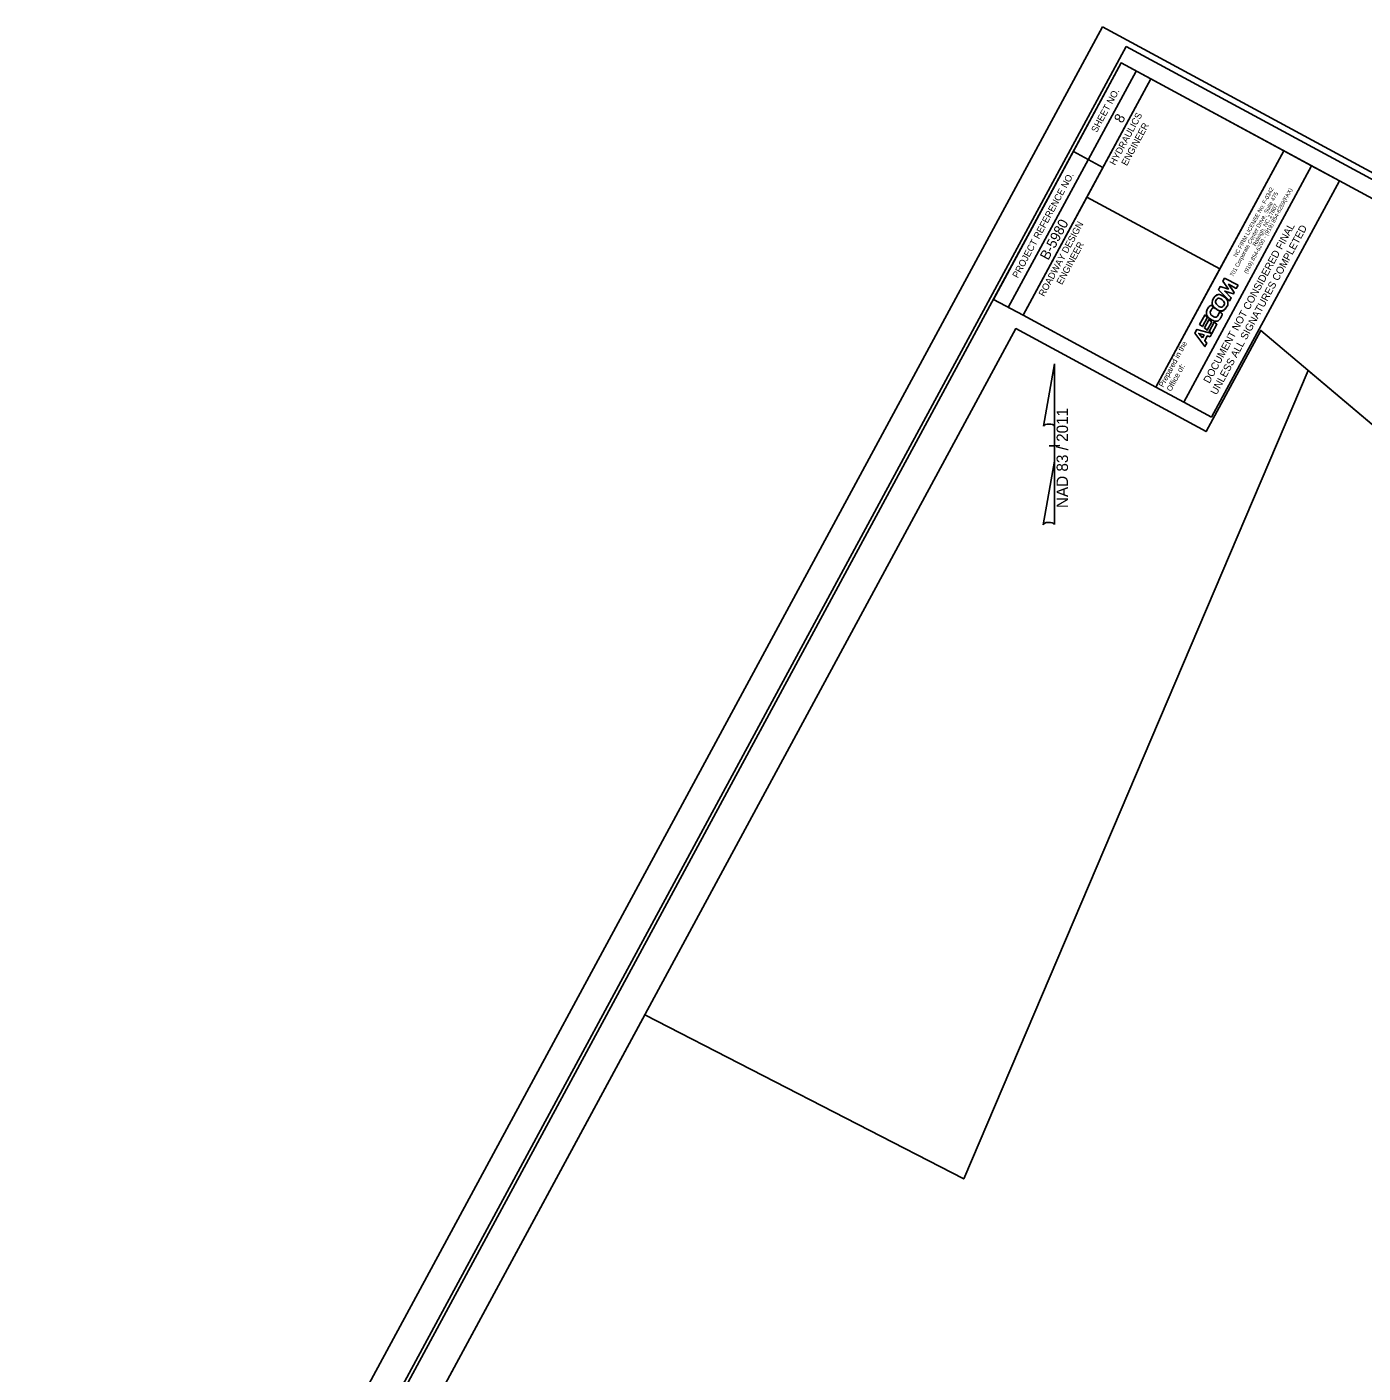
# Model space of a CAD drawing. Extents: x 2345885 to 2347654, y 842598 to 844603.
# Drawn here: x 2345885 to 2346880, y 843601 to 844603 of the extents above; entities that cross this region are included whole.
import ezdxf

# ---------------------------------------------------------------- set-up
doc = ezdxf.new("R2010")
doc.units = 0
for name, color, linetype in [('Default', 7, 'Continuous'), ('Old_Level_49', 7, 'Continuous'), ('Prop North Arrow NAD83 for Plan Sheets CELL', 7, 'Continuous'), ('Sheet Border Standard 30in CELL', 7, 'Continuous'), ('Sheet Clip Boundary CELL', 7, 'Continuous'), ('Sheet Data Field CELL', 7, 'Continuous'), ('Sheet Plot Border Inside CELL', 7, 'Continuous'), ('Sheet Plot Border Outside CELL', 7, 'Continuous'), ('Sheet Profile CELL', 7, 'Continuous'), ('Sheet Sticker Exception Certification CELL', 7, 'Continuous')]:
    doc.layers.add(name, color=color, linetype=linetype)

# ---------------------------------------------------------------- blocks, each defined once
blk = doc.blocks.new('block 2')
at = {"layer": 'Default'}
for p, q in [((0.10234, 0.09375), (0.10197, 0.09133)), ((0.10966, 0.09375), (0.10234, 0.09375)), ((0.10929, 0.09133), (0.10966, 0.09375)), ((0.10114, 0.08576), (0.10078, 0.08333)), ((0.10078, 0.08333), (0.1081, 0.08333)), ((0.10846, 0.08576), (0.10114, 0.08576)), ((0.10137, 0.08733), (0.10174, 0.08975)), ((0.10782, 0.08733), (0.10137, 0.08733)), ((0.10174, 0.08975), (0.10818, 0.08975)), ((0.10197, 0.09133), (0.10929, 0.09133)), ((0.10818, 0.08975), (0.10782, 0.08733)), ((0.1081, 0.08333), (0.10846, 0.08576))]:
    blk.add_line(p, q, dxfattribs=at)
for points in [[(0.10929, 0.09133), (0.10197, 0.09133), (0.10234, 0.09375), (0.10966, 0.09375), (0.10929, 0.09133)], [(0.10846, 0.08576), (0.10114, 0.08576), (0.10078, 0.08333), (0.1081, 0.08333), (0.10846, 0.08576)], [(0.10782, 0.08733), (0.10137, 0.08733), (0.10174, 0.08975), (0.10818, 0.08975), (0.10782, 0.08733)]]:
    blk.add_lwpolyline(points, dxfattribs=at)
blk = doc.blocks.new('block 3')
at = {"layer": 'Default'}
blk.add_open_spline([(0.12275, 0.09393), (0.12554, 0.09373), (0.12726, 0.09146), (0.12695, 0.08843), (0.12663, 0.08531), (0.12411, 0.08298), (0.12127, 0.08318), (0.11848, 0.08338), (0.11676, 0.08565), (0.11707, 0.08868), (0.11739, 0.0918), (0.11991, 0.09413), (0.12275, 0.09393)], degree=3, dxfattribs=at)

msp = doc.modelspace()

# ---------------------------------------------------------------- linework, layer by layer
at = {"layer": 'Old_Level_49'}
for p, q in [((2346773.3, 844409.6), (2346772.1, 844407.3)), ((2346772.1, 844407.3), (2346780.3, 844398.9)), ((2346779.5, 844407.7), (2346773.3, 844409.6)), ((2346776.7, 844415.8), (2346775.5, 844413.6)), ((2346775.5, 844413.6), (2346779.5, 844407.7)), ((2346786.7, 844410.6), (2346776.7, 844415.8)), ((2346783.8, 844405.3), (2346779.6, 844411.4)), ((2346779.6, 844411.4), (2346785.4, 844408.2)), ((2346785.4, 844408.2), (2346786.7, 844410.6)), ((2346781.7, 844401.3), (2346776.8, 844406.2)), ((2346776.8, 844406.2), (2346783.2, 844404.1)), ((2346780.3, 844398.9), (2346781.7, 844401.3)), ((2346783.2, 844404.1), (2346783.8, 844405.3)), ((2346756.1, 844377.7), (2346754.6, 844375)), ((2346767.2, 844374.6), (2346756.1, 844377.7)), ((2346754.6, 844375), (2346762, 844364.9)), ((2346760.2, 844371.4), (2346757.5, 844374.7)), ((2346757.5, 844374.7), (2346757.5, 844374.7)), ((2346757.5, 844374.7), (2346761.4, 844373.6)), ((2346761.4, 844373.6), (2346760.2, 844371.4)), ((2346761.9, 844369.3), (2346763.8, 844372.9)), ((2346763.4, 844367.4), (2346761.9, 844369.3)), ((2346762, 844364.9), (2346763.4, 844367.4)), ((2346763.8, 844372.9), (2346766, 844372.2)), ((2346766, 844372.2), (2346767.2, 844374.6))]:
    msp.add_line(p, q, dxfattribs=at)
for points in [[(2346786.7, 844410.6), (2346776.7, 844415.8), (2346775.5, 844413.6), (2346779.5, 844407.7), (2346773.3, 844409.6), (2346772.1, 844407.3), (2346780.3, 844398.9), (2346781.7, 844401.3), (2346776.8, 844406.2), (2346783.2, 844404.1), (2346783.8, 844405.3), (2346779.6, 844411.4), (2346785.4, 844408.2), (2346786.7, 844410.6)], [(2346766, 844372.2), (2346767.2, 844374.6), (2346756.1, 844377.7), (2346754.6, 844375), (2346762, 844364.9), (2346763.4, 844367.4), (2346761.9, 844369.3), (2346763.8, 844372.9), (2346766, 844372.2)], [(2346760.2, 844371.4), (2346757.5, 844374.7), (2346757.5, 844374.7), (2346761.4, 844373.6), (2346760.2, 844371.4)]]:
    msp.add_lwpolyline(points, dxfattribs=at)
for points in [[(2346777.2, 844393.2), (2346775.5, 844391.4), (2346772.9, 844391.3), (2346770.5, 844392.9), (2346767.7, 844394.8), (2346766.8, 844398.4), (2346768.5, 844401.1)], [(2346768.5, 844401.1), (2346770.1, 844403.6), (2346773.1, 844404.1), (2346775.9, 844402.2), (2346778.7, 844400.3), (2346779.6, 844396.7), (2346778, 844394.1), (2346777.7, 844393.7), (2346777.5, 844393.4), (2346777.2, 844393.2)], [(2346774.8, 844399.7), (2346773.4, 844401), (2346771.7, 844401.1), (2346770.8, 844399.9), (2346769.7, 844398.7), (2346770.1, 844396.9), (2346771.7, 844395.5), (2346773.2, 844394.2), (2346774.8, 844394.2), (2346775.8, 844395.3), (2346776.8, 844396.5), (2346776.4, 844398.4), (2346774.8, 844399.7)], [(2346774.8, 844399.7), (2346773.4, 844401), (2346771.7, 844401.1), (2346770.8, 844399.9), (2346769.7, 844398.7), (2346770.1, 844396.9), (2346771.7, 844395.5), (2346773.2, 844394.2), (2346774.8, 844394.2), (2346775.8, 844395.3), (2346776.8, 844396.5), (2346776.4, 844398.4), (2346774.8, 844399.7)], [(2346772.8, 844391), (2346772.8, 844390.2), (2346772.3, 844389.2), (2346772, 844388.7), (2346771.2, 844387.1), (2346769.5, 844386.6), (2346768, 844387.6), (2346766.3, 844388.5), (2346765.8, 844390.5), (2346766.7, 844392.2), (2346767.2, 844393), (2346767.8, 844393.6), (2346768.7, 844393.9), (2346768.7, 844393.9), (2346766.6, 844395.7), (2346766.6, 844395.7), (2346765.5, 844395), (2346764.8, 844394.3), (2346764.2, 844393.3), (2346762.7, 844390.4), (2346763.8, 844386.8), (2346766.7, 844385), (2346769.6, 844383.4), (2346772.7, 844384.2), (2346774.2, 844387), (2346774.4, 844387.5), (2346775, 844388.5), (2346775, 844389.4), (2346775, 844389.4), (2346772.8, 844391), (2346772.8, 844391)], [(2346772.8, 844391), (2346772.8, 844390.2), (2346772.3, 844389.2), (2346772, 844388.7), (2346771.2, 844387.1), (2346769.5, 844386.6), (2346768, 844387.6), (2346766.3, 844388.5), (2346765.8, 844390.5), (2346766.7, 844392.2), (2346767.2, 844393), (2346767.8, 844393.6), (2346768.7, 844393.9), (2346768.7, 844393.9), (2346766.6, 844395.7), (2346766.6, 844395.7), (2346765.5, 844395), (2346764.8, 844394.3), (2346764.2, 844393.3), (2346762.7, 844390.4), (2346763.8, 844386.8), (2346766.7, 844385), (2346769.6, 844383.4), (2346772.7, 844384.2), (2346774.2, 844387), (2346774.4, 844387.5), (2346775, 844388.5), (2346775, 844389.4), (2346775, 844389.4), (2346772.8, 844391), (2346772.8, 844391)]]:
    msp.add_open_spline(points, degree=3, dxfattribs=at)
at = {"layer": 'Prop North Arrow NAD83 for Plan Sheets CELL'}
for p, q in [((2346641.8, 844305.7), (2346650, 844352.1)), ((2346650.1, 844352.1), (2346650, 844304.3)), ((2346650, 844279.5), (2346650, 844305.7)), ((2346650, 844304.3), (2346650, 844305.7)), ((2346649.6, 844291.1), (2346646, 844291.1)), ((2346646, 844291.1), (2346646, 844291.1)), ((2346646.1, 844291.1), (2346654.1, 844291.2)), ((2346650, 844279.5), (2346641.6, 844232.2)), ((2346650, 844232.5), (2346650, 844279.5))]:
    msp.add_line(p, q, dxfattribs=at)
for centre, start_param, end_param in [((2346645.9, 844305.3), 0.211319, 2.90315), ((2346645.9, 844232.1), 0.19626, 3.136524)]:
    msp.add_ellipse(centre, major_axis=(4.23, 0.01), ratio=0.461128, start_param=start_param, end_param=end_param, dxfattribs=at)
at = {"layer": 'Sheet Border Standard 30in CELL'}
for p, q in [((2346615.7, 844394.1), (2346710.8, 844570.1)), ((2346626.7, 844388.2), (2346721.8, 844564.2)), ((2346626.7, 844388.2), (2346721.8, 844564.2)), ((2346664.1, 844510.1), (2346686.1, 844498.2)), ((2346674.2, 844476.2), (2346773.1, 844422.7))]:
    msp.add_line(p, q, dxfattribs=at)
for points in [[(2346699.7, 844576.1), (2345986.6, 843256.5), (2346910.3, 842757.3), (2347623.5, 844076.9)], [(2346604.6, 844400.1), (2346699.7, 844576.1), (2346721.8, 844564.2), (2346626.7, 844388.2)], [(2346674.2, 844476.2), (2346721.8, 844564.2), (2346820.7, 844510.7), (2346773.2, 844422.7)], [(2346626.7, 844388.2), (2346674.2, 844476.2), (2346773.2, 844422.7), (2346725.6, 844334.7)]]:
    msp.add_lwpolyline(points, close=True, dxfattribs=at)
at = {"layer": 'Sheet Clip Boundary CELL'}
for points in [[(2346122.3, 843455.1), (2346122.3, 843455.1), (2346122.3, 843455.1), (2346732, 842882), (2346732, 842882), (2346732, 842882), (2346732, 842882), (2346732, 842882), (2346843.6, 842821.7), (2347080.7, 843191.4), (2347008.6, 843443.9), (2347008.6, 843443.9), (2347324.8, 843936.9), (2347067.3, 844154.3), (2346803.6, 844377), (2346803.6, 844377), (2346762.9, 844301.7), (2346621.3, 844378.3)], [(2346122.3, 843455.1), (2346122.3, 843455.1), (2346122.3, 843455.1), (2346732, 842882), (2346732, 842882), (2346732, 842882), (2346732, 842882), (2346732, 842882), (2346843.6, 842821.7), (2347088.8, 843163), (2347008.6, 843443.9), (2347008.6, 843443.9), (2347324.8, 843936.9), (2347067.3, 844154.3), (2346838.9, 844347.2), (2346838.9, 844347.2), (2346582.5, 843745.3), (2346345.2, 843867.4)]]:
    msp.add_lwpolyline(points, close=True, dxfattribs=at)
at = {"layer": 'Sheet Plot Border Inside CELL'}
msp.add_lwpolyline([(2346703.4, 844588.3), (2345911.1, 843122.2), (2346839.3, 842620.6), (2347631.6, 844086.7)], close=True, dxfattribs=at)
at = {"layer": 'Sheet Plot Border Outside CELL'}
msp.add_lwpolyline([(2346685.8, 844602.9), (2345885.2, 843121.4), (2346852.9, 842598.4), (2347653.5, 844079.9)], close=True, dxfattribs=at)
at = {"layer": 'Sheet Profile CELL'}
msp.add_line((2346725.6, 844334.7), (2346746.3, 844323.5), dxfattribs=at)
at = {"layer": 'Sheet Sticker Exception Certification CELL'}
for p, q in [((2346725.6, 844334.7), (2346820.7, 844510.7)), ((2346820.7, 844510.7), (2346841.4, 844499.5)), ((2346841.4, 844499.5), (2346746.3, 844323.5)), ((2346746.3, 844323.5), (2346841.4, 844499.5)), ((2346841.4, 844499.5), (2346862.1, 844488.3)), ((2346862.1, 844488.3), (2346767, 844312.3)), ((2346746.3, 844323.5), (2346725.6, 844334.7)), ((2346767, 844312.3), (2346746.3, 844323.5))]:
    msp.add_line(p, q, dxfattribs=at)

# ---------------------------------------------------------------- block references
at = {"layer": 'Old_Level_49', "xscale": 1084.8432715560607, "yscale": 1084.8432715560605, "rotation": 61.60882803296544}
for name in ['block 3', 'block 2']:
    msp.add_blockref(name, (2346794.8, 844235.4), dxfattribs=at)

# ---------------------------------------------------------------- texts
at = {"layer": 'Old_Level_49'}
for s, height, p in [('701 Corporate Center Drive, Suite 475', 3.013, (2346783, 844416.6)), ('NC FIRM LICENSE No: F-0342', 3.013, (2346785.7, 844431.2)), ('(919) 854-6200 - (919) 854-6259(FAX)', 3.013, (2346793.4, 844419)), ('Raleigh, NC 27607', 3.013, (2346799.9, 844439.3)), ('Prepared in the ', 4.018, (2346731, 844334.3)), ('Office of:', 4.02, (2346736.8, 844331.2))]:
    msp.add_text(s, height=height, rotation=61.6088, dxfattribs=at).set_placement(p)
at = {"layer": 'Prop North Arrow NAD83 for Plan Sheets CELL'}
msp.add_text('NAD 83 / 2011', height=8.501, rotation=89.9519, dxfattribs=at).set_placement((2346660.1, 844244.7))
at = {"layer": 'Sheet Border Standard 30in CELL'}
for s, p in [('SHEET NO.', (2346681.5, 844523.8)), ('HYDRAULICS', (2346695.1, 844499.5)), ('ENGINEER', (2346703.9, 844499.1)), ('PROJECT REFERENCE NO.', (2346622.8, 844415.5)), ('ROADWAY DESIGN', (2346642.3, 844401.8)), ('ENGINEER', (2346655.6, 844410.5))]:
    msp.add_text(s, height=5, rotation=61.6124, dxfattribs=at).set_placement(p)
at = {"layer": 'Sheet Data Field CELL'}
for s, p in [('8', (2346700.5, 844530.7)), ('B-5980', (2346645.4, 844428.7))]:
    msp.add_text(s, height=7.5, rotation=61.6124, dxfattribs=at).set_placement(p)
at = {"layer": 'Sheet Sticker Exception Certification CELL'}
for s, p in [('DOCUMENT NOT CONSIDERED FINAL', (2346765.4, 844337.1)), ('UNLESS ALL SIGNATURES COMPLETED', (2346770.7, 844328.5))]:
    msp.add_text(s, height=5.5, rotation=61.6124, dxfattribs=at).set_placement(p)

doc.saveas('drawing.dxf')
